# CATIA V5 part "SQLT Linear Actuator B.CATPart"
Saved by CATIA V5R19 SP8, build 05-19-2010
Part number: SQLT Linear Actuator Sup B
Publications: "Plan.1", "Droite.1", "Plan.2", "Droite.3"
Bounding box of the stored display mesh (mm): x 0 to 0, y 0 to 450, z 600 to 900
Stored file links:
  G:\EU_thinkMotion\CFAO_2010\MMS_groupe3\MMS_groupe3\A reprendre\fovide\fovide\SQLT Linear Actuator B.CATPart
  G:\EU_thinkMotion\CFAO_2010\MMS_groupe3\MMS_groupe3\A reprendre\fovide\fovide\fovide.CATProduct
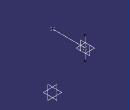
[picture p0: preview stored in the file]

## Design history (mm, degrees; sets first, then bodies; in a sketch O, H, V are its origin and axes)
Set1
  Point1 "Point.B": linked copy from another document
  Point2 "Point.A": linked copy from another document
Set2 "set Linear Actuator B"
  Line1: type PtPt, FirstPoint Point1, SecondPoint Point2
  Plane1: type OffsetPt, RefPlane yz-plane, RefPoint Point1
  Plane2: type OffsetPt, RefPlane xy-plane, RefPoint Point1
  Line2: type Normal, RefPoint Point1, RefSkin Plane2, Start -150, End 150
Body1 (main body)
